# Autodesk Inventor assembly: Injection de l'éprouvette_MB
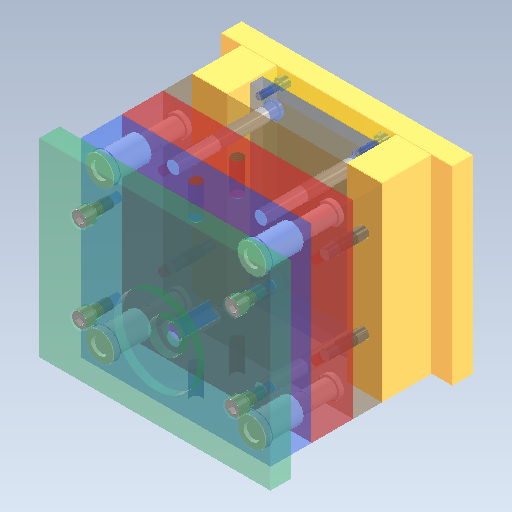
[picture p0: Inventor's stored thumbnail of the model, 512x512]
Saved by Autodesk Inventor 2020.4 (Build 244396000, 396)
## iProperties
Created: 2021-10
Part Number: Injection de l'éprouvette_MB
Document SubType Name: Assembly
Designer: mel
Author: mel
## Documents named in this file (16)
- D:\travail\année 2020-2021\itec\prépa injection plastique eduscol\dossier de travail\Ensemble des pièces de l'activité\Conception de moule1\Mo\FUTABA_SA-S 1\Injection de l'éprouvette_MB.iam
- C:\Users\mel\Documents\Inventor\Content Center Files\R2020\fr-FR\JIS 1176\JIS 1176 M8x25.ipt
- C:\Users\mel\Documents\Inventor\Content Center Files\R2020\fr-FR\GBA\M-GBA 20x49.ipt
- D:\travail\année 2020-2021\itec\prépa injection plastique eduscol\dossier de travail\Ensemble des pièces de l'activité\Conception de moule1\Mo\FUTABA_SA-S 1\Injection de l'éprouvette_MB_SA-SB1.ipt
- D:\travail\année 2020-2021\itec\prépa injection plastique eduscol\dossier de travail\Ensemble des pièces de l'activité\Conception de moule1\Mo\FUTABA_SA-S 1\Injection de l'éprouvette_MB_SA-SB2.ipt
- D:\travail\année 2020-2021\itec\prépa injection plastique eduscol\dossier de travail\Ensemble des pièces de l'activité\Conception de moule1\Mo\FUTABA_SA-S 1\Injection de l'éprouvette_MB_SA-EP.ipt
- C:\Users\mel\Documents\Inventor\Content Center Files\R2020\fr-FR\GPA\M-GPA20x97x39.ipt
- D:\travail\année 2020-2021\itec\prépa injection plastique eduscol\dossier de travail\Ensemble des pièces de l'activité\Conception de moule1\Mo\FUTABA_SA-S 1\Injection de l'éprouvette_MB_SA-ERP.ipt
- D:\travail\année 2020-2021\itec\prépa injection plastique eduscol\dossier de travail\Ensemble des pièces de l'activité\Conception de moule1\Mo\FUTABA_SA-S 1\Injection de l'éprouvette_MB_SA-BCP.ipt
- C:\Users\mel\Documents\Inventor\Content Center Files\R2020\fr-FR\JIS 1176\JIS 1176 M12x25.ipt
- D:\travail\année 2020-2021\itec\prépa injection plastique eduscol\dossier de travail\Ensemble des pièces de l'activité\Conception de moule1\Mo\FUTABA_SA-S 1\Injection de l'éprouvette_MB_RPN.ipt
- D:\travail\année 2020-2021\itec\prépa injection plastique eduscol\dossier de travail\Ensemble des pièces de l'activité\Conception de moule1\Mo\FUTABA_SA-S 1\Injection de l'éprouvette_MB_SA-S-AP.ipt
- D:\travail\année 2020-2021\itec\prépa injection plastique eduscol\dossier de travail\Ensemble des pièces de l'activité\Conception de moule1\Mo\FUTABA_SA-S 1\Injection de l'éprouvette_MB_SA-S-BP.ipt
- D:\travail\année 2020-2021\itec\prépa injection plastique eduscol\dossier de travail\Ensemble des pièces de l'activité\Conception de moule1\Mo\FUTABA_SA-S 1\Injection de l'éprouvette_MB_SA-TCP.ipt
- D:\travail\année 2020-2021\itec\prépa injection plastique eduscol\dossier de travail\Ensemble des pièces de l'activité\Conception de moule1\Mo\FUTABA_SA-S 1\Injection de l'éprouvette_MB_SA-SP.ipt
- C:\Users\mel\Documents\Inventor\Content Center Files\R2020\fr-FR\JIS 1176\JIS 1176 M12x120.ipt
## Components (33 placed, 15 different names)
1. Injection de l'éprouvette_MB_SA-SB1:1 — Affleurement:1, Affleurement:3, Placage:1, Placage:5
2. Injection de l'éprouvette_MB_SA-SB2:2 — Affleurement:2, Affleurement:4, Placage:2, Placage:6
3. Injection de l'éprouvette_MB_SA-EP:1 — Logement:1, Affleurement:5, Affleurement:6, Ejection, Placage:4
4. Injection de l'éprouvette_MB_SA-ERP:1 — Logement:7, Affleurement:7, Affleurement:8, Placage:4
5. Injection de l'éprouvette_MB_SA-BCP:1 — Logement:8, Ejection, Affleurement:9, Affleurement:10, Placage:5, Placage:6
6. Injection de l'éprouvette_MB_SA-S-AP:1 — Logement:2, Logement:5, Affleurement:11, Affleurement:12, Placage:7, PL1, Affleurement:19
7. Injection de l'éprouvette_MB_SA-S-BP:1 — Logement:3, Logement:4, Affleurement:13, Affleurement:14, PL1, Placage:9
8. Injection de l'éprouvette_MB_SA-TCP:1 — Logement:6, Placage:7, Affleurement:15, Affleurement:16
9. Injection de l'éprouvette_MB_SA-SP:1 — Placage:1, Placage:2, Affleurement:17, Affleurement:18, Placage:9
10. GPA 20x97x39:1 — Logement:3
11. GPA 20x97x39:3
12. JIS 1176 M12x25:1 — Logement:6
13. JIS 1176 M12x25:2
14. JIS 1176 M12x25:3
15. JIS 1176 M12x25:4
16. JIS 1176 M8x25:1 — Logement:1
17. JIS 1176 M8x25:2
18. JIS 1176 M8x25:3
19. JIS 1176 M8x25:4
20. JIS 1176 M12x120:1 — Logement:8
21. JIS 1176 M12x120:2
22. JIS 1176 M12x120:3
23. JIS 1176 M12x120:4
24. GBA 20x49:1 — Logement:2
25. GBA 20x49:3
26. GPA 20x97x39:2 — Logement:4
27. GPA 20x97x39:4
28. Injection de l'éprouvette_MB_RPN:1 — Logement:7
29. Injection de l'éprouvette_MB_RPN:2
30. Injection de l'éprouvette_MB_RPN:3
31. Injection de l'éprouvette_MB_RPN:4
32. GBA 20x49:2 — Logement:5
33. GBA 20x49:4
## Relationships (36: Flush 19, Mate 9, Insert 8)
- Logement:1 [Insert]: Injection de l'éprouvette_MB_SA-EP:1 ↔ JIS 1176 M8x25:1
- Logement:2 [Insert]: Injection de l'éprouvette_MB_SA-S-AP:1 ↔ GBA 20x49:1
- Logement:3 [Insert]: Injection de l'éprouvette_MB_SA-S-BP:1 ↔ GPA 20x97x39:1
- Logement:4 [Insert]: Injection de l'éprouvette_MB_SA-S-BP:1 ↔ GPA 20x97x39:2
- Logement:5 [Insert]: Injection de l'éprouvette_MB_SA-S-AP:1 ↔ GBA 20x49:2
- Logement:6 [Insert]: Injection de l'éprouvette_MB_SA-TCP:1 ↔ JIS 1176 M12x25:1
- Logement:7 [Insert]: Injection de l'éprouvette_MB_SA-ERP:1 ↔ Injection de l'éprouvette_MB_RPN:1
- Logement:8 [Insert]: Injection de l'éprouvette_MB_SA-BCP:1 ↔ JIS 1176 M12x120:1
- Affleurement:1 [Flush]: Injection de l'éprouvette_MB_SA-SB1:1
- Affleurement:2 [Flush]: Injection de l'éprouvette_MB_SA-SB2:2
- Affleurement:3 [Flush]: Injection de l'éprouvette_MB_SA-SB1:1
- Affleurement:4 [Flush]: Injection de l'éprouvette_MB_SA-SB2:2
- Placage:1 [Mate]: Injection de l'éprouvette_MB_SA-SB1:1 ↔ Injection de l'éprouvette_MB_SA-SP:1
- Placage:2 [Mate]: Injection de l'éprouvette_MB_SA-SB2:2 ↔ Injection de l'éprouvette_MB_SA-SP:1
- Affleurement:5 [Flush]: Injection de l'éprouvette_MB_SA-EP:1
- Affleurement:6 [Flush]: Injection de l'éprouvette_MB_SA-EP:1
- Ejection [Mate]: Injection de l'éprouvette_MB_SA-EP:1 ↔ Injection de l'éprouvette_MB_SA-BCP:1
- Affleurement:7 [Flush]: Injection de l'éprouvette_MB_SA-ERP:1
- Affleurement:8 [Flush]: Injection de l'éprouvette_MB_SA-ERP:1
- Placage:4 [Mate]: Injection de l'éprouvette_MB_SA-EP:1 ↔ Injection de l'éprouvette_MB_SA-ERP:1
- Affleurement:9 [Flush]: Injection de l'éprouvette_MB_SA-BCP:1
- Affleurement:10 [Flush]: Injection de l'éprouvette_MB_SA-BCP:1
- Placage:5 [Mate]: Injection de l'éprouvette_MB_SA-SB1:1 ↔ Injection de l'éprouvette_MB_SA-BCP:1
- Placage:6 [Mate]: Injection de l'éprouvette_MB_SA-SB2:2 ↔ Injection de l'éprouvette_MB_SA-BCP:1
- Affleurement:11 [Flush]: Injection de l'éprouvette_MB_SA-S-AP:1
- Affleurement:12 [Flush]: Injection de l'éprouvette_MB_SA-S-AP:1
- Placage:7 [Mate]: Injection de l'éprouvette_MB_SA-S-AP:1 ↔ Injection de l'éprouvette_MB_SA-TCP:1
- Affleurement:13 [Flush]: Injection de l'éprouvette_MB_SA-S-BP:1
- Affleurement:14 [Flush]: Injection de l'éprouvette_MB_SA-S-BP:1
- PL1 [Mate]: Injection de l'éprouvette_MB_SA-S-AP:1 ↔ Injection de l'éprouvette_MB_SA-S-BP:1
- Affleurement:15 [Flush]: Injection de l'éprouvette_MB_SA-TCP:1
- Affleurement:16 [Flush]: Injection de l'éprouvette_MB_SA-TCP:1
- Affleurement:17 [Flush]: Injection de l'éprouvette_MB_SA-SP:1
- Affleurement:18 [Flush]: Injection de l'éprouvette_MB_SA-SP:1
- Placage:9 [Mate]: Injection de l'éprouvette_MB_SA-S-BP:1 ↔ Injection de l'éprouvette_MB_SA-SP:1
- Affleurement:19 [Flush]: Injection de l'éprouvette_MB_SA-S-AP:1
